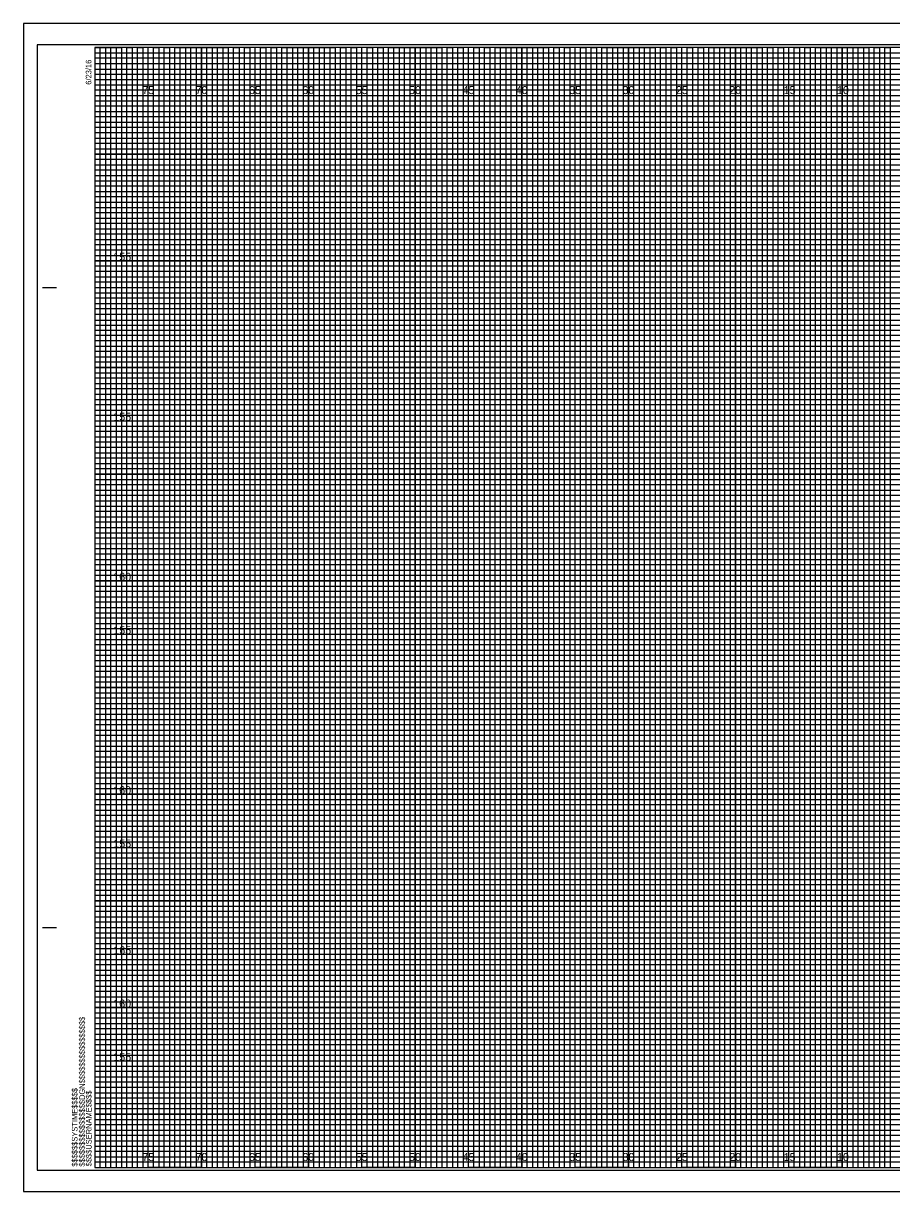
# Model space of a CAD drawing. Extents: x -7 to 162, y 108 to 217.
# Drawn here: x -6.7 to 74.6, y 107.7 to 217.2 of the extents above; entities that cross this region are included whole.
import ezdxf

# ---------------------------------------------------------------- set-up
doc = ezdxf.new("R2010")
doc.units = 0
for name, color, linetype in [('Prop CMT Conc Surface', 7, 'Continuous'), ('Prop CMT Pvmt Course 1', 7, 'Continuous'), ('Prop CMT Slope Grass', 7, 'Continuous'), ('Prop XS Elevation Labels', 7, 'Continuous'), ('Prop XS Hydro Elevations', 7, 'Continuous'), ('Prop XS SE Text', 7, 'Continuous'), ('Prop XS Side Slope Text', 7, 'Continuous'), ('Sheet Cutting Line CELL', 7, 'Continuous'), ('Sheet DOT Grid CELL', 7, 'Continuous'), ('Sheet Plot Border Inside CELL', 7, 'Continuous'), ('Sheet Plot Border Outside CELL', 7, 'Continuous')]:
    doc.layers.add(name, color=color, linetype=linetype)

msp = doc.modelspace()

# ---------------------------------------------------------------- linework, layer by layer
at = {"layer": 'Prop CMT Conc Surface'}
for p, q in [((5, 215), (0, 215)), ((5, 110), (5, 215)), ((15, 215), (10, 215)), ((10, 215), (10, 110)), ((15, 110), (15, 215)), ((25, 215), (20, 215)), ((20, 215), (20, 110)), ((25, 110), (25, 215)), ((35, 215), (30, 215)), ((30, 215), (30, 110)), ((35, 110), (35, 215)), ((45, 215), (40, 215)), ((40, 215), (40, 110)), ((45, 110), (45, 215)), ((55, 215), (50, 215)), ((50, 215), (50, 110)), ((55, 110), (55, 215)), ((65, 215), (60, 215)), ((60, 215), (60, 110)), ((65, 110), (65, 215)), ((75, 215), (70, 215)), ((70, 215), (70, 110)), ((10, 110), (5, 110)), ((20, 110), (15, 110)), ((30, 110), (25, 110)), ((40, 110), (35, 110)), ((50, 110), (45, 110)), ((60, 110), (55, 110)), ((70, 110), (65, 110))]:
    msp.add_line(p, q, dxfattribs=at)
for points in [[(0, 210), (160, 210), (160, 205), (0, 205)], [(0, 200), (160, 200), (160, 195), (0, 195)], [(0, 190), (160, 190), (160, 185), (0, 185)], [(0, 180), (160, 180), (160, 175), (0, 175)], [(0, 170), (160, 170), (160, 165), (0, 165)], [(0, 160), (160, 160), (160, 155), (0, 155)], [(0, 150), (160, 150), (160, 145), (0, 145)], [(0, 140), (160, 140), (160, 135), (0, 135)], [(0, 130), (160, 130), (160, 125), (0, 125)], [(0, 120), (160, 120), (160, 115), (0, 115)]]:
    msp.add_lwpolyline(points, dxfattribs=at)
at = {"layer": 'Prop CMT Slope Grass'}
for points in [[(0, 215), (2.5, 215), (2.5, 110), (7.5, 110), (7.5, 215), (12.5, 215), (12.5, 110), (17.5, 110), (17.5, 215), (22.5, 215), (22.5, 110), (27.5, 110), (27.5, 215), (32.5, 215), (32.5, 110), (37.5, 110), (37.5, 215), (42.5, 215), (42.5, 110), (47.5, 110), (47.5, 215), (52.5, 215), (52.5, 110), (57.5, 110), (57.5, 215), (62.5, 215), (62.5, 110), (67.5, 110), (67.5, 215), (72.5, 215), (72.5, 110), (77.5, 110)], [(0, 212.5), (137.5, 212.5)], [(0, 202.5), (160, 202.5), (160, 207.5), (0, 207.5)], [(0, 192.5), (160, 192.5), (160, 197.5), (0, 197.5)], [(0, 182.5), (160, 182.5), (160, 187.5), (0, 187.5)], [(0, 172.5), (160, 172.5), (160, 177.5), (0, 177.5)], [(0, 162.5), (160, 162.5), (160, 167.5), (0, 167.5)], [(0, 152.5), (160, 152.5), (160, 157.5), (0, 157.5)], [(0, 142.5), (160, 142.5), (160, 147.5), (0, 147.5)], [(0, 132.5), (160, 132.5), (160, 137.5), (0, 137.5)], [(0, 122.5), (160, 122.5), (160, 127.5), (0, 127.5)], [(0, 112.5), (160, 112.5), (160, 117.5), (0, 117.5)]]:
    msp.add_lwpolyline(points, dxfattribs=at)
at = {"layer": 'Prop XS Hydro Elevations'}
for points in [[(0, 110), (0.5, 110), (0.5, 215), (1, 215), (1, 110)], [(1, 110), (1.5, 110), (1.5, 215), (2, 215), (2, 110)], [(2.5, 110), (3, 110), (3, 215), (3.5, 215), (3.5, 110)], [(3.5, 110), (4, 110), (4, 215), (4.5, 215), (4.5, 110)], [(5, 110), (5.5, 110), (5.5, 215), (6, 215), (6, 110)], [(6, 110), (6.5, 110), (6.5, 215), (7, 215), (7, 110)], [(7.5, 110), (8, 110), (8, 215), (8.5, 215), (8.5, 110)], [(8.5, 110), (9, 110), (9, 215), (9.5, 215), (9.5, 110)], [(10, 110), (10.5, 110), (10.5, 215), (11, 215), (11, 110)], [(11, 110), (11.5, 110), (11.5, 215), (12, 215), (12, 110)], [(12.5, 110), (13, 110), (13, 215), (13.5, 215), (13.5, 110)], [(13.5, 110), (14, 110), (14, 215), (14.5, 215), (14.5, 110)], [(15, 110), (15.5, 110), (15.5, 215), (16, 215), (16, 110)], [(16, 110), (16.5, 110), (16.5, 215), (17, 215), (17, 110)], [(17.5, 110), (18, 110), (18, 215), (18.5, 215), (18.5, 110)], [(18.5, 110), (19, 110), (19, 215), (19.5, 215), (19.5, 110)], [(20, 110), (20.5, 110), (20.5, 215), (21, 215), (21, 110)], [(21, 110), (21.5, 110), (21.5, 215), (22, 215), (22, 110)], [(22.5, 110), (23, 110), (23, 215), (23.5, 215), (23.5, 110)], [(23.5, 110), (24, 110), (24, 215), (24.5, 215), (24.5, 110)], [(25, 110), (25.5, 110), (25.5, 215), (26, 215), (26, 110)], [(26, 110), (26.5, 110), (26.5, 215), (27, 215), (27, 110)], [(27.5, 110), (28, 110), (28, 215), (28.5, 215), (28.5, 110)], [(28.5, 110), (29, 110), (29, 215), (29.5, 215), (29.5, 110)], [(30, 110), (30.5, 110), (30.5, 215), (31, 215), (31, 110)], [(31, 110), (31.5, 110), (31.5, 215), (32, 215), (32, 110)], [(32.5, 110), (33, 110), (33, 215), (33.5, 215), (33.5, 110)], [(33.5, 110), (34, 110), (34, 215), (34.5, 215), (34.5, 110)], [(35, 110), (35.5, 110), (35.5, 215), (36, 215), (36, 110)], [(36, 110), (36.5, 110), (36.5, 215), (37, 215), (37, 110)], [(37.5, 110), (38, 110), (38, 215), (38.5, 215), (38.5, 110)], [(38.5, 110), (39, 110), (39, 215), (39.5, 215), (39.5, 110)], [(40, 110), (40.5, 110), (40.5, 215), (41, 215), (41, 110)], [(41, 110), (41.5, 110), (41.5, 215), (42, 215), (42, 110)], [(42.5, 110), (43, 110), (43, 215), (43.5, 215), (43.5, 110)], [(43.5, 110), (44, 110), (44, 215), (44.5, 215), (44.5, 110)], [(45, 110), (45.5, 110), (45.5, 215), (46, 215), (46, 110)], [(46, 110), (46.5, 110), (46.5, 215), (47, 215), (47, 110)], [(47.5, 110), (48, 110), (48, 215), (48.5, 215), (48.5, 110)], [(48.5, 110), (49, 110), (49, 215), (49.5, 215), (49.5, 110)], [(50, 110), (50.5, 110), (50.5, 215), (51, 215), (51, 110)], [(51, 110), (51.5, 110), (51.5, 215), (52, 215), (52, 110)], [(52.5, 110), (53, 110), (53, 215), (53.5, 215), (53.5, 110)], [(53.5, 110), (54, 110), (54, 215), (54.5, 215), (54.5, 110)], [(55, 110), (55.5, 110), (55.5, 215), (56, 215), (56, 110)], [(56, 110), (56.5, 110), (56.5, 215), (57, 215), (57, 110)], [(57.5, 110), (58, 110), (58, 215), (58.5, 215), (58.5, 110)], [(58.5, 110), (59, 110), (59, 215), (59.5, 215), (59.5, 110)], [(60, 110), (60.5, 110), (60.5, 215), (61, 215), (61, 110)], [(61, 110), (61.5, 110), (61.5, 215), (62, 215), (62, 110)], [(62.5, 110), (63, 110), (63, 215), (63.5, 215), (63.5, 110)], [(63.5, 110), (64, 110), (64, 215), (64.5, 215), (64.5, 110)], [(65, 110), (65.5, 110), (65.5, 215), (66, 215), (66, 110)], [(66, 110), (66.5, 110), (66.5, 215), (67, 215), (67, 110)], [(67.5, 110), (68, 110), (68, 215), (68.5, 215), (68.5, 110)], [(68.5, 110), (69, 110), (69, 215), (69.5, 215), (69.5, 110)], [(70, 110), (70.5, 110), (70.5, 215), (71, 215), (71, 110)], [(71, 110), (71.5, 110), (71.5, 215), (72, 215), (72, 110)], [(72.5, 110), (73, 110), (73, 215), (73.5, 215), (73.5, 110)], [(73.5, 110), (74, 110), (74, 215), (74.5, 215), (74.5, 110)]]:
    msp.add_lwpolyline(points, dxfattribs=at)
at = {"layer": 'Prop XS SE Text'}
for p, q in [((0, 214.5), (130, 214.5)), ((130, 213.99), (0, 213.99)), ((0, 213.99), (0, 213.5)), ((0, 213.5), (130, 213.5)), ((130, 212.94), (0, 212.94)), ((0, 212.94), (0, 212)), ((0, 212), (160, 212))]:
    msp.add_line(p, q, dxfattribs=at)
for points in [[(0, 211.5), (135, 211.5), (160, 211.5), (160, 211), (0, 211)], [(0, 210.5), (160, 210.5), (160, 209.5), (0, 209.5)], [(0, 209), (160, 209), (160, 208.5), (0, 208.49)], [(0, 208), (160, 208), (160, 207), (0, 207)], [(0, 206.5), (160, 206.5), (160, 206), (0, 206)], [(0, 205.5), (160, 205.5), (160, 204.5), (0, 204.5)], [(0, 204), (160, 204), (160, 203.5), (0, 203.5)], [(0, 203), (160, 203), (160, 202), (0, 202)], [(0, 201.5), (160, 201.5), (160, 201), (0, 201)], [(0, 200.5), (160, 200.5), (160, 199.5), (0, 199.5)], [(0, 199), (160, 199), (160, 198.5), (0, 198.5)], [(0, 198), (160, 198), (160, 196.97), (160, 196.5), (160, 196), (0, 196)], [(0, 197), (160, 197), (160, 196.5), (0, 196.5)], [(0, 195.5), (160, 195.5), (160, 194.5), (0, 194.52)], [(0, 194.52), (160, 194.5), (160, 194), (0, 194)], [(0, 193.5), (160, 193.5), (160, 193), (0, 193)], [(0, 192), (160, 192), (160, 191.5), (0, 191.5)], [(0, 191), (160, 191), (160, 190.5), (0, 190.5)], [(-0.04, 189.44), (160, 189.44), (160, 188.94), (-0.04, 188.94)], [(0, 188.5), (160, 188.5), (160, 188), (0, 188)], [(0, 187), (160, 187), (160, 186.5), (0, 186.5)], [(0, 186), (160, 186), (160, 185.5), (0, 185.5)], [(0, 184.5), (160, 184.5), (160, 184), (0, 184)], [(0, 183.5), (160, 183.5), (160, 183), (0, 183)], [(0, 182), (160, 182), (160, 181.5), (0, 181.5)], [(0, 181), (160, 181), (160, 180.5), (0, 180.5)], [(0, 179.5), (160, 179.5), (160, 178.99), (0, 179)], [(0, 178.5), (160, 178.5), (160, 178), (0, 178)], [(0, 177), (160, 177), (160, 176.5), (0, 176.5)], [(0, 176), (160, 176), (160, 175.5), (0, 175.5)], [(0, 174.5), (160, 174.5), (160, 174), (0, 174)], [(0, 173.5), (160, 173.5), (160, 173), (0, 173)], [(0, 172), (160, 172), (160, 171.5), (0, 171.5)], [(0, 171), (160, 171), (160, 170.5), (0, 170.5)], [(0, 169.5), (160, 169.5), (160, 169), (0, 169)], [(0, 168.5), (160.03, 168.46), (160, 168), (0, 168)], [(0, 167), (160, 167), (160, 166.5), (0, 166.5)], [(0, 166), (160, 166), (160, 165.5), (0, 165.5)], [(0, 164.5), (160, 164.5), (160, 164), (0, 164)], [(0, 163.5), (160, 163.5), (160, 163), (0, 163)], [(0, 162), (160, 162), (160, 161.5), (0, 161.5)], [(0, 161), (160, 161), (160, 160.5), (0, 160.5)], [(0, 159.5), (160, 159.5), (160, 159), (0, 159)], [(0, 158.5), (160, 158.5), (160, 158), (0, 158)], [(0, 157), (160, 157), (160, 156.5), (0, 156.5)], [(0, 156), (160, 156), (160, 155.5), (0, 155.5)], [(0, 154.5), (160, 154.5), (160, 154), (0, 154)], [(0, 153.5), (160, 153.5), (160, 153), (0, 153)], [(0, 152), (160, 152), (160, 151.5), (0, 151.5)], [(0, 151), (160, 151), (160, 150.5), (0, 150.5)], [(0, 149.5), (160, 149.5), (160, 148.99), (0, 149)], [(0, 148.5), (160, 148.5), (160, 148), (0, 148)], [(0, 147), (160, 147), (160, 146.5), (0, 146.5)], [(0, 146), (160, 146), (160, 145.5), (0, 145.5)], [(0, 144.5), (160, 144.5), (160, 144), (0, 144)], [(0, 143.5), (160, 143.5), (160, 143), (0, 143)], [(0, 142), (160, 142), (160, 141.5), (0, 141.5)], [(0, 141), (160, 141), (160, 140.5), (0, 140.5)], [(0, 139.5), (160, 139.5), (160, 139), (0, 139)], [(0, 138.5), (160.03, 138.46), (160, 138), (0, 138)], [(0, 137), (160, 137), (160, 136.5), (0, 136.5)], [(0, 136), (160, 136), (160, 135.5), (0, 135.5)], [(0, 134.5), (160, 134.5), (160, 134), (0, 134)], [(0, 133.5), (160, 133.5), (160, 133), (0, 133)], [(0, 132), (160, 132), (160, 131.5), (0, 131.5)], [(0, 131), (160, 131), (160, 130.5), (0, 130.5)], [(0, 129.5), (160, 129.5), (160, 129), (0, 129)], [(0, 128.5), (160, 128.5), (160, 128), (0, 128)], [(0, 127), (160, 127), (160, 126.5), (0, 126.5)], [(0, 126), (160, 126), (160, 125.5), (0, 125.5)], [(0, 124.5), (160, 124.5), (160, 124), (0, 124)], [(0, 123.5), (160, 123.5), (160, 123), (0, 123)], [(0, 122), (160, 122), (160, 121.5), (0, 121.5)], [(0, 121), (160, 121), (160, 120.5), (0, 120.5)], [(0, 119.5), (160, 119.5), (160, 119), (0, 119)], [(0, 118.5), (160, 118.5), (160, 118), (0, 118)], [(0, 117), (160, 117), (160, 116.5), (0, 116.5)], [(0, 116), (160, 116), (160, 115.5), (0, 115.5)], [(0, 114.5), (160, 114.5), (160, 114), (0, 114)], [(0, 113.5), (160, 113.5), (160, 113), (0, 113)], [(0, 112), (160, 112), (160, 111.5), (0, 111.5)], [(0, 111), (160, 111), (160, 110.5), (0, 110.5)]]:
    msp.add_lwpolyline(points, dxfattribs=at)
at = {"layer": 'Prop XS Side Slope Text'}
for p, q in [((-4.9, 192.5), (-3.65, 192.5)), ((-4.85, 192.5), (-3.6, 192.5)), ((-4.9, 132.5), (-3.65, 132.5)), ((-4.85, 132.5), (-3.6, 132.5)), ((0, 110), (0, 110)), ((0, 110), (0, 110)), ((0, 110), (0, 110)), ((0, 110), (0, 110)), ((0, 110), (0, 110)), ((0, 110), (0, 110)), ((0, 110), (0, 110))]:
    msp.add_line(p, q, dxfattribs=at)
msp.add_lwpolyline([(160, 215), (0, 215), (0, 110), (160, 110)], close=True, dxfattribs=at)
at = {"layer": 'Sheet Cutting Line CELL'}
for p, q in [((161.65, 217.25), (-6.7, 217.25)), ((-6.7, 217.25), (-6.7, 107.75)), ((-6.7, 107.75), (161.65, 107.75))]:
    msp.add_line(p, q, dxfattribs=at)
at = {"layer": 'Sheet DOT Grid CELL'}
for p, q in [((5, 110), (5, 215)), ((10, 110), (10, 215)), ((15, 110), (15, 215)), ((20, 110), (20, 215)), ((25, 110), (25, 215)), ((30, 110), (30, 215)), ((35, 110), (35, 215)), ((40, 110), (40, 215)), ((45, 110), (45, 215)), ((50, 110), (50, 215)), ((55, 110), (55, 215)), ((60, 110), (60, 215)), ((65, 110), (65, 215)), ((70, 110), (70, 215)), ((0, 210), (160, 210)), ((0, 205), (160, 205)), ((0, 200), (160, 200)), ((0, 195), (160, 195)), ((0, 190), (160, 190)), ((0, 185), (160, 185)), ((0, 180), (160, 180)), ((0, 175), (160, 175)), ((0, 170), (160, 170)), ((0, 165), (160, 165)), ((0, 160), (160, 160)), ((0, 155), (160, 155)), ((0, 150), (160, 150)), ((0, 145), (160, 145)), ((0, 140), (160, 140)), ((0, 135), (160, 135)), ((0, 130), (160, 130)), ((0, 125), (160, 125)), ((0, 120), (160, 120)), ((0, 115), (160, 115))]:
    msp.add_line(p, q, dxfattribs=at)
at = {"layer": 'Sheet Plot Border Inside CELL'}
msp.add_lwpolyline([(-5.4, 109.75), (161.2, 109.75), (161.2, 215.25), (-5.4, 215.25)], close=True, dxfattribs=at)
at = {"layer": 'Sheet Plot Border Outside CELL'}
msp.add_lwpolyline([(-6.7, 107.75), (161.65, 107.75), (161.65, 217.25), (-6.7, 217.25)], close=True, dxfattribs=at)

# ---------------------------------------------------------------- texts
at = {"layer": 'Prop CMT Pvmt Course 1'}
for s, p in [('75', (4.44, 210.62)), ('70', (9.43, 210.62)), ('65', (14.44, 210.62)), ('60', (19.43, 210.62)), ('55', (24.44, 210.62)), ('50', (29.43, 210.62)), ('45', (34.44, 210.62)), ('40', (39.43, 210.62)), ('35', (44.44, 210.62)), ('30', (49.43, 210.62)), ('25', (54.44, 210.62)), ('20', (59.43, 210.62)), ('15', (64.53, 210.62)), ('10', (69.52, 210.62)), ('75', (4.44, 110.62)), ('70', (9.43, 110.62)), ('65', (14.44, 110.62)), ('60', (19.43, 110.62)), ('55', (24.44, 110.62)), ('50', (29.43, 110.62)), ('45', (34.44, 110.62)), ('40', (39.43, 110.62)), ('35', (44.44, 110.62)), ('30', (49.43, 110.62)), ('25', (54.44, 110.62)), ('20', (59.43, 110.62)), ('15', (64.53, 110.62)), ('10', (69.52, 110.62))]:
    msp.add_text(s, height=0.75, dxfattribs=at).set_placement(p)
at = {"layer": 'Prop XS Elevation Labels'}
for s, p in [('155', (1.73, 195)), ('155', (1.73, 180)), ('160', (1.72, 165)), ('155', (1.73, 160)), ('160', (1.72, 145)), ('155', (1.73, 140)), ('165', (1.73, 130)), ('160', (1.72, 125)), ('155', (1.73, 120))]:
    msp.add_text(s, height=0.75, dxfattribs=at).set_placement(p)
at = {"layer": 'Prop XS Side Slope Text'}
for s, p in [('6/23/16', (-0.33, 211.5)), ('$$$$$$$$$$$$$$$$DGN$$$$$$$$$$$$$$$$', (-0.94, 110.09)), ('$$$$$$SYSTIME$$$$$', (-1.63, 110.09)), ('$$$$USERNAME$$$$', (-0.31, 110.12))]:
    msp.add_text(s, height=0.525, rotation=90, dxfattribs=at).set_placement(p)

doc.saveas('drawing.dxf')
